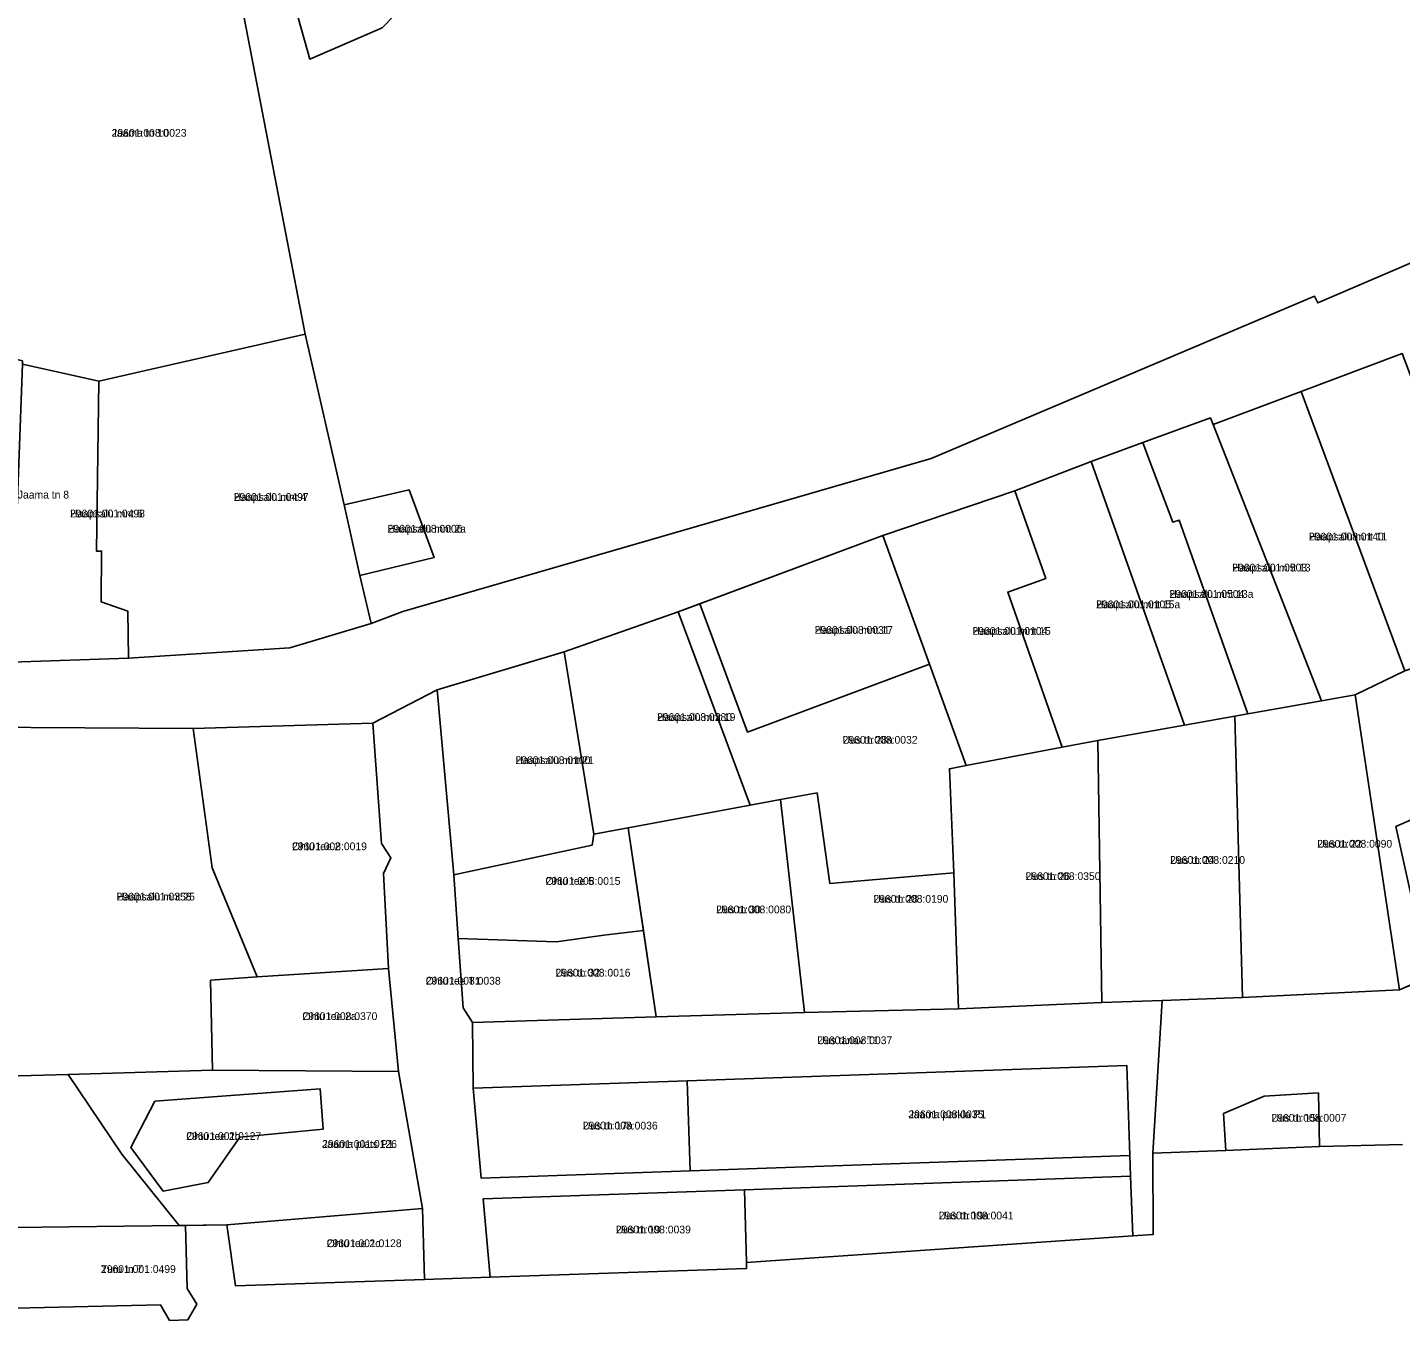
# Model space of a CAD drawing. Extents: x 518839 to 525192, y 6573164 to 6576561.
# Drawn here: x 523676.7 to 523942.5, y 6574299.7 to 6574550.6 of the extents above; entities that cross this region are included whole.
import ezdxf

# ---------------------------------------------------------------- set-up
doc = ezdxf.new("R2010")
doc.units = 0
for name, color, linetype in [('L_AADRESS', 7, 'Continuous'), ('PIIR', 7, 'Continuous'), ('TUNNUS', 7, 'Continuous')]:
    doc.layers.add(name, color=color, linetype=linetype)

msp = doc.modelspace()

# ---------------------------------------------------------------- linework, layer by layer
at = {"layer": 'PIIR'}
for points in [[(523720.84, 6574581.96), (523731.37, 6574544.41), (523745.35, 6574550.51), (523754.71, 6574560.19), (523730.74, 6574582.64)], [(523720.84, 6574581.96), (523730.74, 6574582.64), (523754.71, 6574560.19), (523745.35, 6574550.51), (523731.37, 6574544.41)], [(523679.09, 6574579.83), (523715.18, 6574570.22), (523730.41, 6574491.16), (523690.47, 6574482.07), (523675.73, 6574485.36), (523675.69, 6574485.98), (523655.53, 6574491)], [(523690.04, 6574449.11), (523690.47, 6574482.07), (523730.41, 6574491.16), (523737.98, 6574458.09), (523741.03, 6574444.43), (523743.19, 6574435.09), (523727.46, 6574430.39), (523696.24, 6574428.38), (523696.07, 6574437.5), (523690.95, 6574439.29), (523691.03, 6574449.13)], [(523673.58, 6574427.58), (523675.73, 6574485.36), (523690.47, 6574482.07), (523690.04, 6574449.11), (523691.03, 6574449.13), (523690.95, 6574439.29), (523696.07, 6574437.5), (523696.24, 6574428.38)], [(523923.27, 6574480.06), (523942.85, 6574487.39), (523963.4, 6574433.26), (523955.11, 6574429.92), (523943.34, 6574425.96)], [(523923.27, 6574480.06), (523943.34, 6574425.96), (523933.73, 6574421.28), (523927.24, 6574420.14), (523906.23, 6574473.68)], [(523893.81, 6574467.01), (523892.63, 6574470.14), (523905.71, 6574474.92), (523906.23, 6574473.68), (523927.24, 6574420.14), (523912.95, 6574417.61), (523899.65, 6574455.14), (523898.44, 6574454.73)], [(523900.7, 6574415.42), (523882.61, 6574466.48), (523892.63, 6574470.14), (523893.81, 6574467.01), (523898.44, 6574454.73), (523899.65, 6574455.14), (523912.95, 6574417.61), (523910.46, 6574417.17)], [(523873.83, 6574443.8), (523867.87, 6574460.81), (523882.61, 6574466.48), (523900.7, 6574415.42), (523883.89, 6574412.46), (523877.01, 6574411.12), (523866.48, 6574441.19)], [(523737.98, 6574458.09), (523750.58, 6574460.99), (523755.4, 6574447.87), (523741.03, 6574444.43)], [(523851.31, 6574427.22), (523842.27, 6574452.15), (523867.87, 6574460.81), (523873.83, 6574443.8), (523866.48, 6574441.19), (523877.01, 6574411.12), (523858.43, 6574407.57)], [(523806.85, 6574438.91), (523842.27, 6574452.15), (523851.31, 6574427.22), (523816.1, 6574414.06)], [(523786.34, 6574394.28), (523780.59, 6574429.6), (523802.63, 6574437.34), (523816.57, 6574399.89), (523792.98, 6574395.51)], [(523802.63, 6574437.34), (523806.85, 6574438.91), (523816.1, 6574414.06), (523851.31, 6574427.22), (523858.43, 6574407.57), (523855.19, 6574406.95), (523856.04, 6574386.81), (523832.03, 6574384.72), (523829.57, 6574402.27), (523822.47, 6574400.99), (523816.57, 6574399.89)], [(523780.59, 6574429.6), (523786.34, 6574394.28), (523785.99, 6574392.16), (523759.21, 6574386.42), (523755.97, 6574422.25)], [(523942.36, 6574364.13), (523933.73, 6574421.28), (523943.34, 6574425.96), (523955.11, 6574429.92), (523965.83, 6574406.37), (523941.65, 6574395.76), (523948.05, 6574366.62)], [(523743.57, 6574415.77), (523755.97, 6574422.25), (523759.21, 6574386.42), (523760.08, 6574374.11), (523761.02, 6574360.68), (523762.82, 6574357.82), (523762.95, 6574345.09), (523764.53, 6574327.64), (523804.98, 6574329.05), (523890.13, 6574332.02), (523890.27, 6574328.03), (523815.52, 6574325.42), (523764.89, 6574323.65), (523766.26, 6574308.49), (523753.55, 6574308.06), (523753.13, 6574321.77), (523748.51, 6574348.33), (523746.57, 6574368.26), (523745.59, 6574386.69), (523747.04, 6574389.74), (523745.19, 6574392.51)], [(523910.46, 6574417.17), (523912.95, 6574417.61), (523927.24, 6574420.14), (523933.73, 6574421.28), (523942.36, 6574364.13), (523911.95, 6574362.67)], [(523883.89, 6574412.46), (523900.7, 6574415.42), (523910.46, 6574417.17), (523911.95, 6574362.67), (523896.4, 6574362.09), (523884.67, 6574361.67)], [(523668.57, 6574397.63), (523666.73, 6574415.03), (523708.75, 6574414.77), (523712.43, 6574387.75), (523721.13, 6574366.63), (523712.13, 6574365.98), (523712.47, 6574348.57), (523684.56, 6574347.77), (523672.6, 6574347.44), (523670.88, 6574365.74), (523669.08, 6574385.57)], [(523708.75, 6574414.77), (523743.57, 6574415.77), (523745.19, 6574392.51), (523747.04, 6574389.74), (523745.59, 6574386.69), (523746.57, 6574368.26), (523721.13, 6574366.63), (523712.43, 6574387.75)], [(523856.04, 6574386.81), (523855.19, 6574406.95), (523858.43, 6574407.57), (523877.01, 6574411.12), (523883.89, 6574412.46), (523884.67, 6574361.67), (523856.91, 6574360.49)], [(523948.05, 6574366.62), (523941.65, 6574395.76), (523965.83, 6574406.37), (523977.96, 6574379.73)], [(523792.98, 6574395.51), (523816.57, 6574399.89), (523822.47, 6574400.99), (523827.1, 6574359.75), (523798.4, 6574358.89)], [(523822.47, 6574400.99), (523829.57, 6574402.27), (523832.03, 6574384.72), (523856.04, 6574386.81), (523856.91, 6574360.49), (523827.1, 6574359.75)], [(523759.21, 6574386.42), (523785.99, 6574392.16), (523786.34, 6574394.28), (523792.98, 6574395.51), (523795.93, 6574375.61), (523788.27, 6574374.73), (523779.1, 6574373.44), (523760.08, 6574374.11)], [(523760.08, 6574374.11), (523779.1, 6574373.44), (523788.27, 6574374.73), (523795.93, 6574375.61), (523798.4, 6574358.89), (523762.82, 6574357.82), (523761.02, 6574360.68)], [(523712.13, 6574365.98), (523721.13, 6574366.63), (523746.57, 6574368.26), (523748.51, 6574348.33), (523712.47, 6574348.57)], [(523762.82, 6574357.82), (523798.4, 6574358.89), (523827.1, 6574359.75), (523856.91, 6574360.49), (523884.67, 6574361.67), (523896.4, 6574362.09), (523894.56, 6574332.49), (523894.66, 6574316.75), (523890.67, 6574316.47), (523890.27, 6574328.03), (523890.13, 6574332.02), (523889.52, 6574349.51), (523804.37, 6574346.54), (523762.95, 6574345.09)], [(523804.37, 6574346.54), (523889.52, 6574349.51), (523890.13, 6574332.02), (523804.98, 6574329.05)], [(523602.37, 6574310.61), (523601.66, 6574343.44), (523627.14, 6574343.91), (523627.04, 6574346.36), (523641.08, 6574346.71), (523672.6, 6574347.44), (523684.56, 6574347.77), (523694.97, 6574332.28), (523706.05, 6574318.49), (523674.12, 6574318.12), (523674.33, 6574302.46), (523674.36, 6574300.29), (523650.57, 6574299.69), (523649.98, 6574317.14), (523618.1, 6574316.06), (523610.6, 6574311.8)], [(523694.97, 6574332.28), (523684.56, 6574347.77), (523712.47, 6574348.57), (523748.51, 6574348.33), (523753.13, 6574321.77), (523715.26, 6574318.61), (523706.05, 6574318.49)], [(523701.35, 6574342.55), (523696.65, 6574333.57), (523702.93, 6574325.15), (523711.66, 6574326.79), (523717.77, 6574335.58), (523733.92, 6574337.14), (523733.33, 6574344.97)], [(523696.65, 6574333.57), (523701.35, 6574342.55), (523733.33, 6574344.97), (523733.92, 6574337.14), (523717.77, 6574335.58), (523711.66, 6574326.79), (523702.93, 6574325.15)], [(523762.95, 6574345.09), (523804.37, 6574346.54), (523804.98, 6574329.05), (523764.53, 6574327.64)], [(523926.86, 6574333.79), (523908.68, 6574333.01), (523908.22, 6574340.16), (523916.12, 6574343.54), (523926.64, 6574344.16)], [(523815.52, 6574325.42), (523890.27, 6574328.03), (523890.67, 6574316.47), (523815.87, 6574311.3)], [(523764.89, 6574323.65), (523815.52, 6574325.42), (523815.87, 6574311.3), (523815.86, 6574310.15), (523766.26, 6574308.49)], [(523716.92, 6574306.83), (523715.26, 6574318.61), (523753.13, 6574321.77), (523753.55, 6574308.06)], [(523702.41, 6574303.1), (523674.33, 6574302.46), (523674.12, 6574318.12), (523706.05, 6574318.49), (523707.28, 6574318.5), (523707.62, 6574306.28), (523709.45, 6574303.26), (523707.74, 6574300.22), (523704.18, 6574300.1)]]:
    msp.add_lwpolyline(points, close=True, dxfattribs=at)
for points in [[(524055.5, 6574559.93), (524048.74, 6574545.24), (523960.55, 6574511.82), (523926.54, 6574497.21), (523925.89, 6574498.49), (523851.65, 6574467.07), (523749.34, 6574437.4), (523743.19, 6574435.09), (523741.03, 6574444.43), (523755.4, 6574447.87), (523750.58, 6574460.99), (523737.98, 6574458.09), (523730.41, 6574491.16), (523715.18, 6574570.22)], [(523673.58, 6574427.58), (523696.24, 6574428.38), (523727.46, 6574430.39), (523743.19, 6574435.09), (523749.34, 6574437.4), (523851.65, 6574467.07), (523925.89, 6574498.49), (523926.54, 6574497.21), (523960.55, 6574511.82)], [(523942.85, 6574487.39), (523923.27, 6574480.06), (523906.23, 6574473.68), (523905.71, 6574474.92), (523892.63, 6574470.14), (523882.61, 6574466.48), (523867.87, 6574460.81), (523842.27, 6574452.15), (523802.63, 6574437.34), (523780.59, 6574429.6), (523755.97, 6574422.25), (523743.57, 6574415.77), (523708.75, 6574414.77), (523666.73, 6574415.03)], [(523942.9, 6574334.18), (523926.86, 6574333.79), (523926.64, 6574344.16), (523916.12, 6574343.54), (523908.22, 6574340.16), (523908.68, 6574333.01), (523894.56, 6574332.49), (523896.4, 6574362.09), (523911.95, 6574362.67), (523942.36, 6574364.13), (523977.96, 6574379.73)], [(523674.33, 6574302.46), (523702.41, 6574303.1), (523704.18, 6574300.1), (523707.74, 6574300.22), (523709.45, 6574303.26), (523707.62, 6574306.28), (523707.28, 6574318.5), (523715.26, 6574318.61), (523716.92, 6574306.83), (523753.55, 6574308.06), (523766.26, 6574308.49), (523815.86, 6574310.15), (523815.87, 6574311.3), (523890.67, 6574316.47), (523894.66, 6574316.75), (523894.56, 6574332.49), (523908.68, 6574333.01), (523926.86, 6574333.79), (523942.9, 6574334.18)]]:
    msp.add_lwpolyline(points, dxfattribs=at)

# ---------------------------------------------------------------- texts
at = {"layer": 'L_AADRESS'}
for s, p in [('Jaama tn 10', (523692.97, 6574529.39)), ('Haapsalu mnt 8 // Jaama tn 8', (523658.52, 6574459.31)), ('Haapsalu mnt 4', (523716.61, 6574458.86)), ('Haapsalu mnt 6', (523684.91, 6574455.65)), ('Haapsalu mnt 2a', (523746.4, 6574452.71)), ('Haapsalu mnt 11', (523924.79, 6574451.19)), ('Haapsalu mnt 13', (523909.94, 6574445.18)), ('Haapsalu mnt 13a', (523897.78, 6574440.07)), ('Haapsalu mnt 15a', (523883.59, 6574438.06)), ('Haapsalu mnt 17', (523829.09, 6574433.1)), ('Haapsalu mnt 15', (523859.64, 6574432.91)), ('Haapsalu mnt 19', (523798.58, 6574416.23)), ('Uus tn 28a', (523834.51, 6574411.82)), ('Haapsalu mnt 21', (523771.16, 6574407.88)), ('Ohtu tee 2', (523727.89, 6574391.19)), ('Uus tn 22', (523926.41, 6574391.68)), ('Uus tn 24', (523897.92, 6574388.54)), ('Uus tn 26', (523869.93, 6574385.41)), ('Ohtu tee 5', (523776.98, 6574384.48)), ('Haapsalu mnt 25', (523693.93, 6574381.45)), ('Uus tn 28', (523840.47, 6574381.01)), ('Uus tn 30', (523810.04, 6574378.96)), ('Uus tn 32', (523778.92, 6574366.71)), ('Ohtu tee T1', (523753.79, 6574365.15)), ('Ohtu tee 2a', (523729.91, 6574358.29)), ('Uus tänav T1', (523829.61, 6574353.62)), ('Jaama parkla P1', (523847.25, 6574339.28)), ('Uus tn 15a', (523917.54, 6574338.59)), ('Ohtu tee 2b', (523707.42, 6574335.06)), ('Uus tn 17a', (523784.19, 6574337.09)), ('Jaama plats P1', (523733.71, 6574333.53)), ('Uus tn 19a', (523853.11, 6574319.67)), ('Uus tn 19', (523790.61, 6574316.96)), ('Ohtu tee 2c', (523734.61, 6574314.3)), ('Turu tn 7', (523690.89, 6574309.3))]:
    msp.add_text(s, height=1.5, dxfattribs=at).set_placement(p)
at = {"layer": 'TUNNUS'}
for s, p in [('29601:008:0023', (523692.97, 6574529.39)), ('29601:001:0497', (523716.61, 6574458.86)), ('29601:001:0498', (523684.91, 6574455.65)), ('29601:008:0006', (523746.4, 6574452.71)), ('29601:008:0140', (523924.79, 6574451.19)), ('29601:001:0503', (523909.94, 6574445.18)), ('29601:001:0504', (523897.78, 6574440.07)), ('29601:001:0105', (523883.59, 6574438.06)), ('29601:008:0031', (523829.09, 6574433.1)), ('29601:001:0104', (523859.64, 6574432.91)), ('29601:008:0280', (523798.58, 6574416.23)), ('29601:008:0032', (523834.51, 6574411.82)), ('29601:008:0100', (523771.16, 6574407.88)), ('29601:008:0019', (523727.89, 6574391.19)), ('29601:008:0090', (523926.41, 6574391.68)), ('29601:008:0210', (523897.92, 6574388.54)), ('29601:008:0350', (523869.93, 6574385.41)), ('29601:008:0015', (523776.98, 6574384.48)), ('29601:001:0358', (523693.93, 6574381.45)), ('29601:008:0190', (523840.47, 6574381.01)), ('29601:008:0080', (523810.04, 6574378.96)), ('29601:008:0016', (523778.92, 6574366.71)), ('29601:008:0038', (523753.79, 6574365.15)), ('29601:008:0370', (523729.91, 6574358.29)), ('29601:008:0037', (523829.61, 6574353.62)), ('29601:008:0035', (523847.25, 6574339.28)), ('29601:008:0007', (523917.54, 6574338.59)), ('29601:001:0127', (523707.42, 6574335.06)), ('29601:008:0036', (523784.19, 6574337.09)), ('29601:001:0126', (523733.71, 6574333.53)), ('29601:008:0041', (523853.11, 6574319.67)), ('29601:008:0039', (523790.61, 6574316.96)), ('29601:001:0128', (523734.61, 6574314.3)), ('29601:001:0499', (523690.89, 6574309.3))]:
    msp.add_text(s, height=1.5, dxfattribs=at).set_placement(p)

doc.saveas('drawing.dxf')
